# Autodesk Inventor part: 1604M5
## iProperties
Shininess: 80.0
Length Units: 11269
Angle Units: 11279
Time Units: 11290
Mass Units: 11284
Length Display Precision: 3
Angle Display Precision: 2
Compacted: True
Company: Pneumax S.p.A.
Part Number: 1604M5
Material: Default
Description: ASTA+ANELLO DOPPIO GIREVOLE Ø4 M5
Document SubType Name: Modellazione
Catalog Web Link: www.pneumaxspa.com
Density: 1.59
Volumn: 0.8648857994912436
Area: 17.092995283760587
PropertySet Name: Model Information
Control State: 0
Master: False
Checked Out: False
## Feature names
1. Revolution6
2. Rivoluzione7 [Revolution]
3. Foro6 [Hole]
4. Serie circolare8 [Circular Pattern]
5. Serie circolare9 [Circular Pattern]
6. Smusso10 [Chamfer]
7. Foro7 [Hole]
8. Estrusione11 [Extrusion]
9. Foro8 [Hole]
